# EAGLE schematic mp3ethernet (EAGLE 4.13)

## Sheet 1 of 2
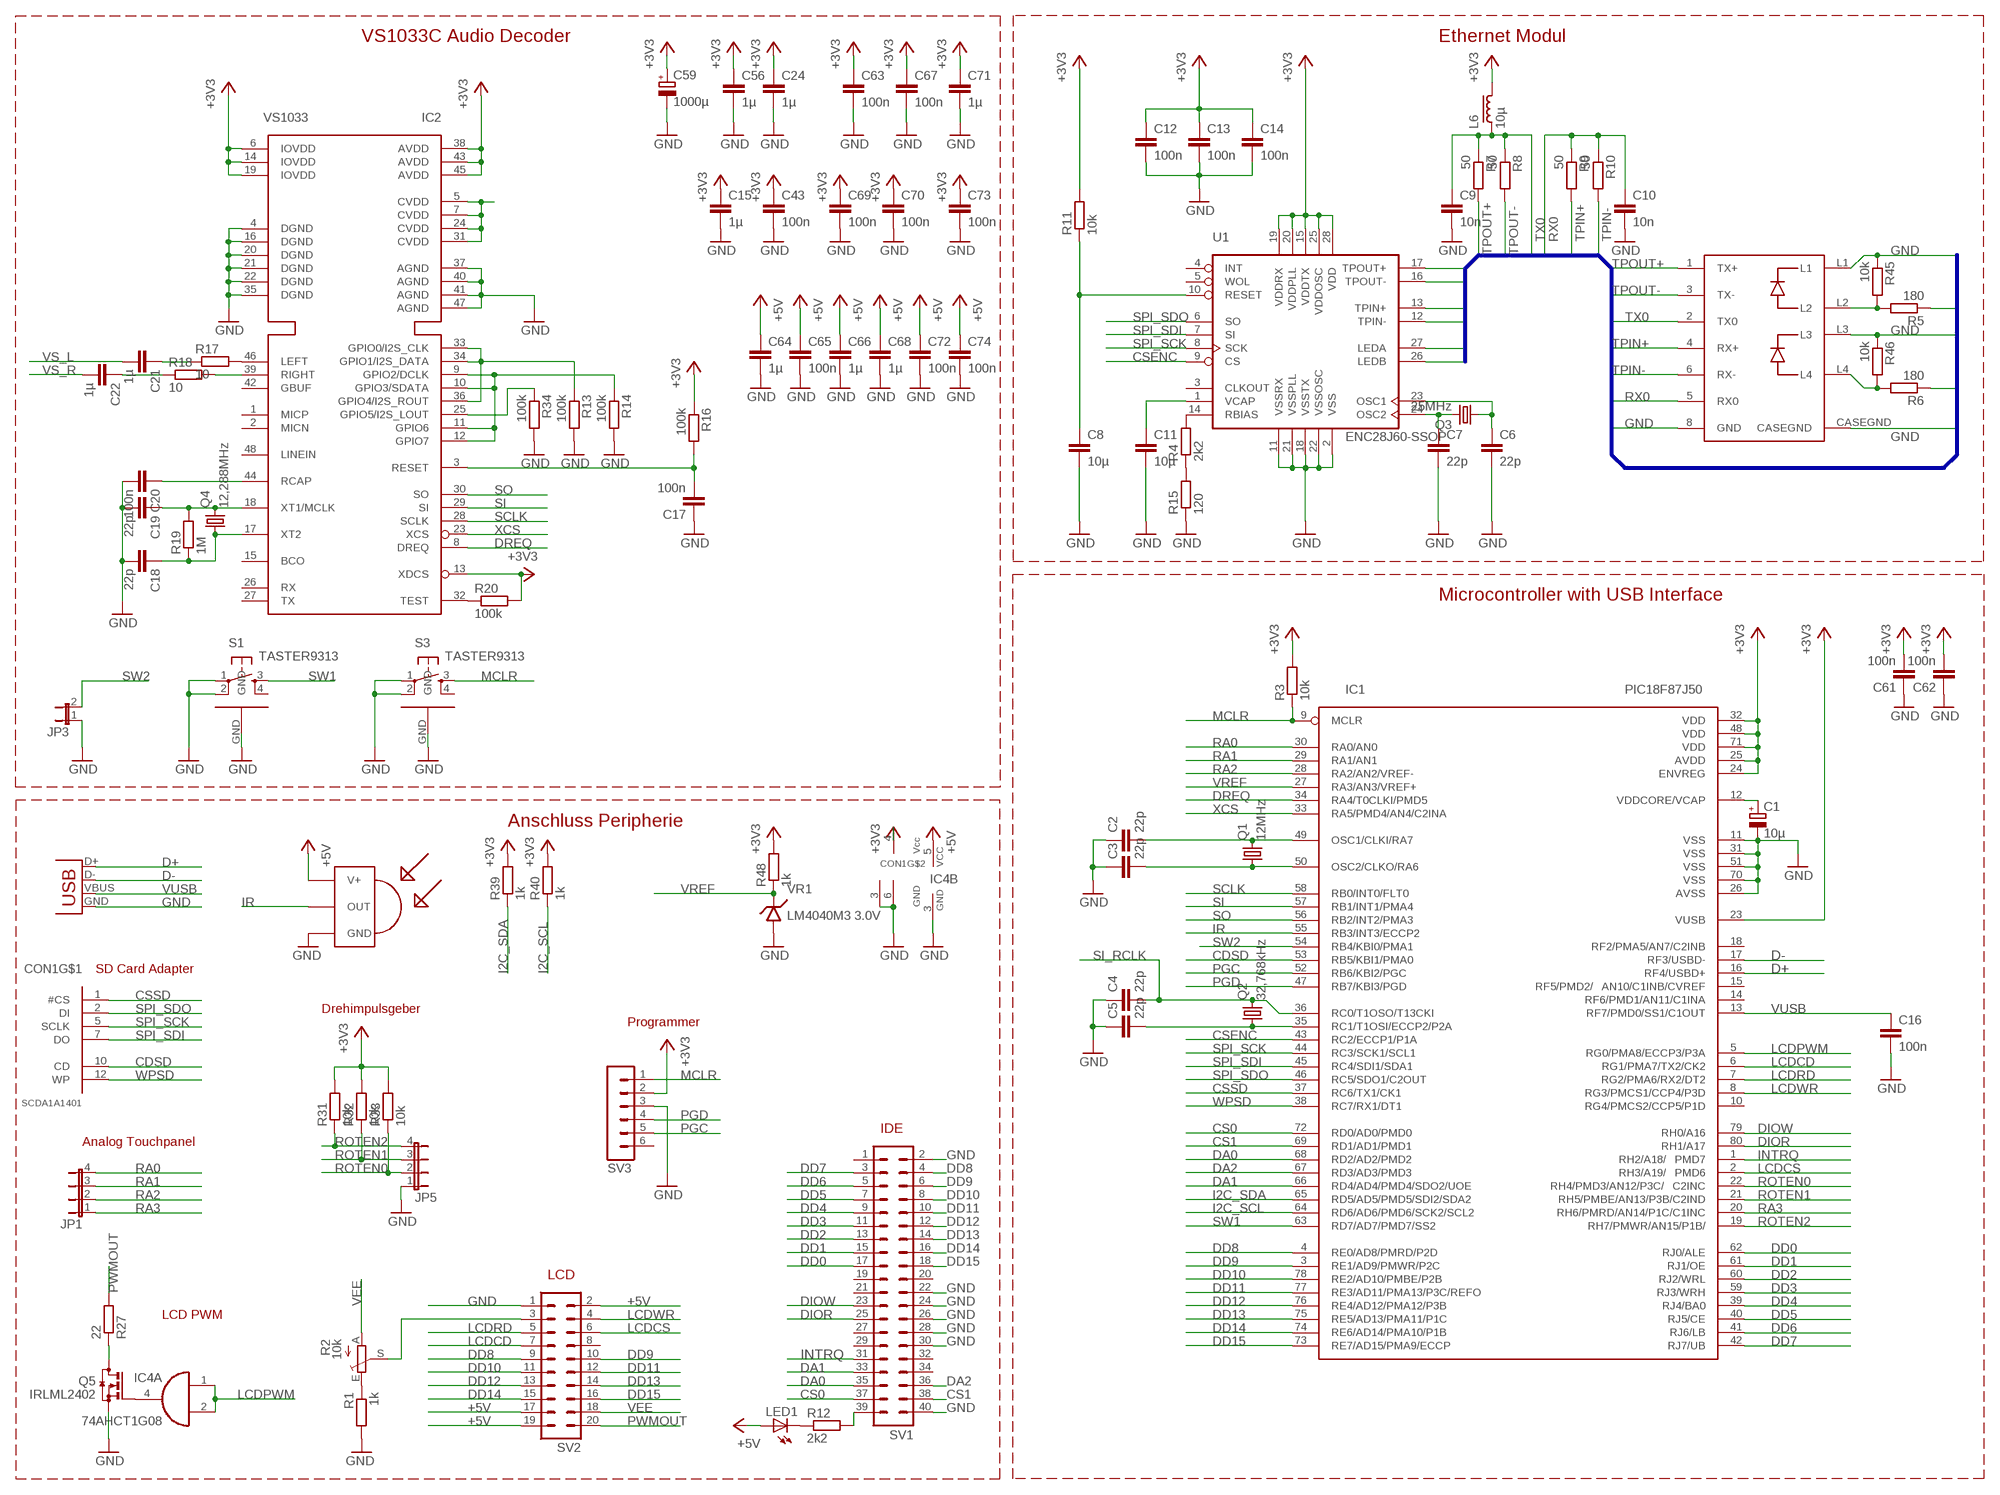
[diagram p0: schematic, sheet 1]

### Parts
BU1  1XRJ45_MM_JACK  [1XRJ45_MM_JACK]
C1  10µ  CPOL-EUE1.8-4  [E1,8-4]
C2  22p  C-EUC0805K  [C0805K]
C3  22p  C-EUC0805K  [C0805K]
C4  22p  C-EUC0805K  [C0805K]
C5  22p  C-EUC0805K  [C0805K]
C6  22p  C-EUC0805K  [C0805K]
C7  22p  C-EUC0805K  [C0805K]
C8  10µ  C-EUC0805K  [C0805K]
C9  10n  C-EUC0805K  [C0805K]
C10  10n  C-EUC0805K  [C0805K]
C11  10µ  C-EUC0805K  [C0805K]
C12  100n  C-EUC0805K  [C0805K]
C13  100n  C-EUC0805K  [C0805K]
C14  100n  C-EUC0805K  [C0805K]
C15  1µ  C-EUC0805K  [C0805K]
C16  100n  C-EUC0805K  [C0805K]
C17  100n  C-EUC0805K  [C0805K]
C18  22p  C-EUC0805K  [C0805K]
C19  22p  C-EUC0805K  [C0805K]
C20  100n  C-EUC0805K  [C0805K]
C21  1µ  C-EUC0805K  [C0805K]
C22  1µ  C-EUC0805K  [C0805K]
C24  1µ  C-EUC0805K  [C0805K]
C43  100n  C-EUC0805K  [C0805K]
C56  1µ  C-EUC0805K  [C0805K]
C59  1000µ  CPOL-EU150CLZ-0810  [150CLZ-0810]
C61  100n  C-EUC0805K  [C0805K]
C62  100n  C-EUC0805K  [C0805K]
C63  100n  C-EUC0805K  [C0805K]
C64  1µ  C-EUC0805K  [C0805K]
C65  100n  C-EUC0805K  [C0805K]
C66  1µ  C-EUC0805K  [C0805K]
C67  100n  C-EUC0805K  [C0805K]
C68  1µ  C-EUC0805K  [C0805K]
C69  100n  C-EUC0805K  [C0805K]
C70  100n  C-EUC0805K  [C0805K]
C71  1µ  C-EUC0805K  [C0805K]
C72  100n  C-EUC0805K  [C0805K]
C73  100n  C-EUC0805K  [C0805K]
C74  100n  C-EUC0805K  [C0805K]
CON1  SCDA1A1401  [SDCA1A1401]
IC1  PIC18F87J50  [SQFP-S-12X12-80]
IC2  VS1033  [SQFP-S-7X7-48]
IC4  74AHCT1G08  74AHTC1G08  [SOT23-5]
IC13  TSOP1836  [TSOP18XX]
JP1  JP4E  [JP4]
JP3  JP1E  [JP1]
JP5  JP4E  [JP4]
L6  10µ  L-PM1210  [PM1210]
LED1  LEDCHIPLED_0805  [CHIPLED_0805]
Q1  12MHz  CRYTALSM49  [SM49]
Q2  32,768kHz  CRYTALTC26V  [TC26V]
Q3  25MHz  CRYTALHC49UP  [HC49UP]
Q4  12,288MHz  CRYTALSM49  [SM49]
Q5  IRLML2402  BSS123  [SOT23]
R1  1k  R-EU_M0805  [M0805]
R2  10k  TRIM_EU-S64W  [S64W]
R3  10k  R-EU_R0805  [R0805]
R4  2k2  R-EU_R0805  [R0805]
R5  180  R-EU_R0805  [R0805]
R6  180  R-EU_R0805  [R0805]
R7  50  R-EU_R0805  [R0805]
R8  50  R-EU_R0805  [R0805]
R9  50  R-EU_R0805  [R0805]
R10  50  R-EU_R0805  [R0805]
R11  10k  R-EU_R0805  [R0805]
R12  2k2  R-EU_R0805  [R0805]
R13  100k  R-EU_R0805  [R0805]
R14  100k  R-EU_R0805  [R0805]
R15  120  R-EU_R0805  [R0805]
R16  100k  R-EU_R0805  [R0805]
R17  10  R-EU_R0805  [R0805]
R18  10  R-EU_R0805  [R0805]
R19  1M  R-EU_R0805  [R0805]
R20  100k  R-EU_R0805  [R0805]
R27  22  R-EU_R0805  [R0805]
R31  10k  R-EU_R0805  [R0805]
R32  10k  R-EU_R0805  [R0805]
R33  10k  R-EU_R0805  [R0805]
R34  100k  R-EU_R0805  [R0805]
R39  1k  R-EU_R0805  [R0805]
R40  1k  R-EU_R0805  [R0805]
R45  10k  R-EU_R0805  [R0805]
R46  10k  R-EU_R0805  [R0805]
R48  1k  R-EU_R0805  [R0805]
S1  TASTER9313  [TASTER9313]
S3  TASTER9313  [TASTER9313]
SV1  ML40  [ML40]
SV2  ML20  [ML20]
SV3  MA06-1  [MA06-1]
U1  ENC28J60-SSOP  [SSOP28]
VR1  LM4040M3 3.0V  LM4040M3  [SOT23]
X1  USB-MB-H  [USB-MB-H]

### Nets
+3V3: C12.1 C13.1 C14.1 C15.1 C24.1 C43.1 C56.1 C59.+ C61.2 C62.2 C63.1 C67.1 C69.1 C70.1 C71.1 C73.1 CON1.4(VCC) IC1.23(VUSB) IC1.24(ENVREG) IC1.25(AVDD) IC1.32(VDD) IC1.48(VDD) IC1.71(VDD) IC2.6(IOVDD) IC2.13(XDCS) IC2.14(IOVDD) IC2.19(IOVDD) IC2.38(AVDD) IC2.43(AVDD) IC2.45(AVDD) L6.2 R3.2 R11.2 R16.1 R20.2 R31.2 R32.2 R33.2 R39.2 R40.2 R48.2 SV3.2 U1.15(VDDTX) U1.19(VDDRX) U1.20(VDDPLL) U1.25(VDDOSC) U1.28(VDD) ; also sheet 2
+5V: C64.1 C65.1 C66.1 C68.1 C72.1 C74.1 IC4.5(B:VCC) IC13.VCC(V+) LED1.A SV2.2 SV2.17 SV2.19 ; also sheet 2
CDSD: CON1.10(CD) IC1.53(RB5/KBI1/PMA0)
CS0: IC1.72(RD0/AD0/PMD0) SV1.37
CS1: IC1.69(RD1/AD1/PMD1) SV1.38
CSENC: IC1.43(RC2/ECCP1/P1A) U1.9(CS)
CSSD: CON1.1(#CS) IC1.37(RC6/TX1/CK1)
D+: IC1.16(RF4/USBD+) X1.D+
D-: IC1.17(RF3/USBD-) X1.D-
DA0: IC1.68(RD2/AD2/PMD2) SV1.35
DA1: IC1.66(RD4/AD4/PMD4/SDO2/UOE) SV1.33
DA2: IC1.67(RD3/AD3/PMD3) SV1.36
DD0: IC1.62(RJ0/ALE) SV1.17
DD1: IC1.61(RJ1/OE) SV1.15
DD2: IC1.60(RJ2/WRL) SV1.13
DD3: IC1.59(RJ3/WRH) SV1.11
DD4: IC1.39(RJ4/BA0) SV1.9
DD5: IC1.40(RJ5/CE) SV1.7
DD6: IC1.41(RJ6/LB) SV1.5
DD7: IC1.42(RJ7/UB) SV1.3
DD8: IC1.4(RE0/AD8/PMRD/P2D) SV1.4 SV2.9
DD9: IC1.3(RE1/AD9/PMWR/P2C) SV1.6 SV2.10
DD10: IC1.78(RE2/AD10/PMBE/P2B) SV1.8 SV2.11
DD11: IC1.77(RE3/AD11/PMA13/P3C/REFO) SV1.10 SV2.12
DD12: IC1.76(RE4/AD12/PMA12/P3B) SV1.12 SV2.13
DD13: IC1.75(RE5/AD13/PMA11/P1C) SV1.14 SV2.14
DD14: IC1.74(RE6/AD14/PMA10/P1B) SV1.16 SV2.15
DD15: IC1.73(RE7/AD15/PMA9/ECCP) SV1.18 SV2.16
DIOR: IC1.80(RH1/A17) SV1.25
DIOW: IC1.79(RH0/A16) SV1.23
DREQ: IC1.34(RA4/T0CLKI/PMD5) IC2.8(DREQ)
GND: BU1.8(GND) BU1.CASEGND BU1.L1 BU1.L3 C1.- C2.1 C3.1 C4.1 C5.1 C6.2 C7.2 C8.2 C9.2 C10.2 C11.2 C12.2 C13.2 C14.2 C15.2 C16.2 C17.1 C18.2 C19.2 C20.2 C24.2 C43.2 C56.2 C59.- C61.1 C62.1 C63.2 C64.2 C65.2 C66.2 C67.2 C68.2 C69.2 C70.2 C71.2 C72.2 C73.2 C74.2 CON1.3(GND) CON1.6(GND) IC1.11(VSS) IC1.26(AVSS) IC1.31(VSS) IC1.51(VSS) IC1.70(VSS) IC2.4(DGND) IC2.16(DGND) IC2.20(DGND) IC2.21(DGND) IC2.22(DGND) IC2.35(DGND) IC2.37(AGND) IC2.40(AGND) IC2.41(AGND) IC2.47(AGND) IC4.3(B:GND) IC13.GND JP3.1 JP5.1 Q5.2(S) R1.2 R13.2 R14.2 R15.1 R34.2 R45.1 R46.1 S1.1(P) S1.2(P1) S1.GND S3.1(P) S3.2(P1) S3.GND SV1.2 SV1.22 SV1.24 SV1.26 SV1.28 SV1.30 SV1.40 SV2.1 SV3.3 U1.2(VSS) U1.11(VSSRX) U1.18(VSSTX) U1.21(VSSPLL) U1.22(VSSOSC) VR1.2 X1.GND ; also sheet 2
I2C_SCL: IC1.64(RD6/AD6/PMD6/SCK2/SCL2) R40.1 ; also sheet 2
I2C_SDA: IC1.65(RD5/AD5/PMD5/SDI2/SDA2) R39.1 ; also sheet 2
INTRQ: IC1.1(RH2/A18/PMD7) SV1.31
IR: IC1.55(RB3/INT3/ECCP2) IC13.OUT
LCDCD: IC1.6(RG1/PMA7/TX2/CK2) SV2.7
LCDCS: IC1.2(RH3/A19/PMD6) SV2.6
LCDPWM: IC1.5(RG0/PMA8/ECCP3/P3A) IC4.1(A:I0) IC4.2(A:I1)
LCDRD: IC1.7(RG2/PMA6/RX2/DT2) SV2.5
LCDWR: IC1.8(RG3/PMCS1/CCP4/P3D) SV2.4
LEDA: R5.1 U1.27(LEDA)
LEDB: R6.1 U1.26(LEDB)
MCLR: IC1.9(MCLR) R3.1 S3.3(S) SV3.1
N$1: C2.2 IC1.49(OSC1/CLKI/RA7) Q1.2
N$2: C3.2 IC1.50(OSC2/CLKO/RA6) Q1.1
N$3: C5.2 IC1.35(RC1/T1OSI/ECCP2/P2A) Q2.1
N$5: R2.S SV2.3
N$7: R12.2 SV1.39
N$8: C17.2 IC2.3(RESET) R16.2
N$9: C1.+ IC1.12(VDDCORE/VCAP)
N$10: IC2.46(LEFT) R17.2
N$11: R1.1 R2.E
N$12: BU1.L2 R5.2 R45.2
N$13: C7.1 Q3.2 U1.24(OSC2)
N$14: C6.1 Q3.1 U1.23(OSC1)
N$15: C8.1 R11.1 U1.10(RESET)
N$16: R4.2 U1.14(RBIAS)
N$17: C11.1 U1.1(VCAP)
N$18: BU1.L4 R6.2 R46.2
N$19: C19.1 IC2.18(XT1/MCLK) Q4.2 R19.2
N$20: C18.1 IC2.17(XT2) Q4.1 R19.1
N$21: Q5.3(D) R27.1
N$22: IC2.39(RIGHT) R18.2
N$23: LED1.C R12.1
N$25: IC2.25(GPIO5/I2S_LOUT) R34.1
N$27: IC4.4(A:O) Q5.1(G)
N$28: C21.1 R17.1
N$29: C20.1 IC2.44(RCAP)
N$30: IC2.32(TEST) R20.1
N$31: C22.1 R18.1
N$55: IC2.33(GPIO0/I2S_CLK) IC2.34(GPIO1/I2S_DATA) IC2.36(GPIO4/I2S_ROUT) R13.1
N$56: IC2.9(GPIO2/DCLK) IC2.10(GPIO3/SDATA) IC2.11(GPIO6) IC2.12(GPIO7) R14.1
N$69: R4.1 R15.2
PGC: IC1.52(RB6/KBI2/PGC) SV3.5
PGD: IC1.47(RB7/KBI3/PGD) SV3.4
PWMOUT: R27.2 SV2.20
RA0: IC1.30(RA0/AN0) JP1.4
RA1: IC1.29(RA1/AN1) JP1.3
RA2: IC1.28(RA2/AN2/VREF-) JP1.2
RA3: IC1.20(RH6/PMRD/AN14/P1C/C1INC) JP1.1
ROTEN0: IC1.22(RH4/PMD3/AN12/P3C/C2INC) JP5.2 R33.1
ROTEN1: IC1.21(RH5/PMBE/AN13/P3B/C2IND) JP5.3 R32.1
ROTEN2: IC1.19(RH7/PMWR/AN15/P1B/) JP5.4 R31.1
RX0: BU1.5(RX0) C10.1 R9.1 R10.1
SCLK: IC1.58(RB0/INT0/FLT0) IC2.28(SCLK)
SI: IC1.57(RB1/INT1/PMA4) IC2.29(SI)
SI_RCLK: C4.2 IC1.36(RC0/T1OSO/T13CKI) Q2.2 ; also sheet 2
SO: IC1.56(RB2/INT2/PMA3) IC2.30(SO)
SPI_SCK: CON1.5(SCLK) IC1.44(RC3/SCK1/SCL1) U1.8(SCK)
SPI_SDI: CON1.7(DO) IC1.45(RC4/SDI1/SDA1) U1.7(SI)
SPI_SDO: CON1.2(DI) IC1.46(RC5/SDO1/C2OUT) U1.6(SO)
SW1: IC1.63(RD7/AD7/PMD7/SS2) S1.3(S)
SW2: IC1.54(RB4/KBI0/PMA1) JP3.2
TPIN+: BU1.4(RX+) R9.2 U1.13(TPIN+)
TPIN-: BU1.6(RX-) R10.2 U1.12(TPIN-)
TPOUT+: BU1.1(TX+) R7.2 U1.17(TPOUT+)
TPOUT-: BU1.3(TX-) R8.2 U1.16(TPOUT-)
TX0: BU1.2(TX0) C9.1 L6.1 R7.1 R8.1
VDD_2,5: IC2.5(CVDD) IC2.7(CVDD) IC2.24(CVDD) IC2.31(CVDD) ; also sheet 2
VEE: R2.A SV2.18
VREF: IC1.27(RA3/AN3/VREF+) R48.1 VR1.1
VS_L: C21.2 ; also sheet 2
VS_R: C22.2 ; also sheet 2
VUSB: C16.1 IC1.13(RF7/PMD0/SS1/C1OUT) X1.VBUS
WPSD: CON1.12(WP) IC1.38(RC7/RX1/DT1)
XCS: IC1.33(RA5/PMD4/AN4/C2INA) IC2.23(XCS)
Unconnected: IC1.10(RG4/PMCS2/CCP5/P1D) IC1.14(RF6/PMD1/AN11/C1INA) IC1.15(RF5/PMD2/AN10/C1INB/CVREF) IC1.18(RF2/PMA5/AN7/C2INB) IC2.1(MICP) IC2.2(MICN) IC2.15(BCO) IC2.26(RX) IC2.27(TX) IC2.42(GBUF) IC2.48(LINEIN) S1.4(S1) S3.4(S1) SV1.1 SV1.19 SV1.20 SV1.21 SV1.27 SV1.29 SV1.32 SV1.34 SV2.8 SV3.6 U1.3(CLKOUT) U1.4(INT) U1.5(WOL)

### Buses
TPOUT+,TPOUT-,TPIN+,TPIN-,LEDA,LEDB,GND,TX0,RX0

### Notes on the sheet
- VS1033C Audio Decoder | Ethernet Modul
- Microcontroller with USB Interface
- Anschluss Peripherie
- SD Card Adapter
- Drehimpulsgeber
- Programmer
- IDE
- Analog Touchpanel
- LCD
- LCD PWM

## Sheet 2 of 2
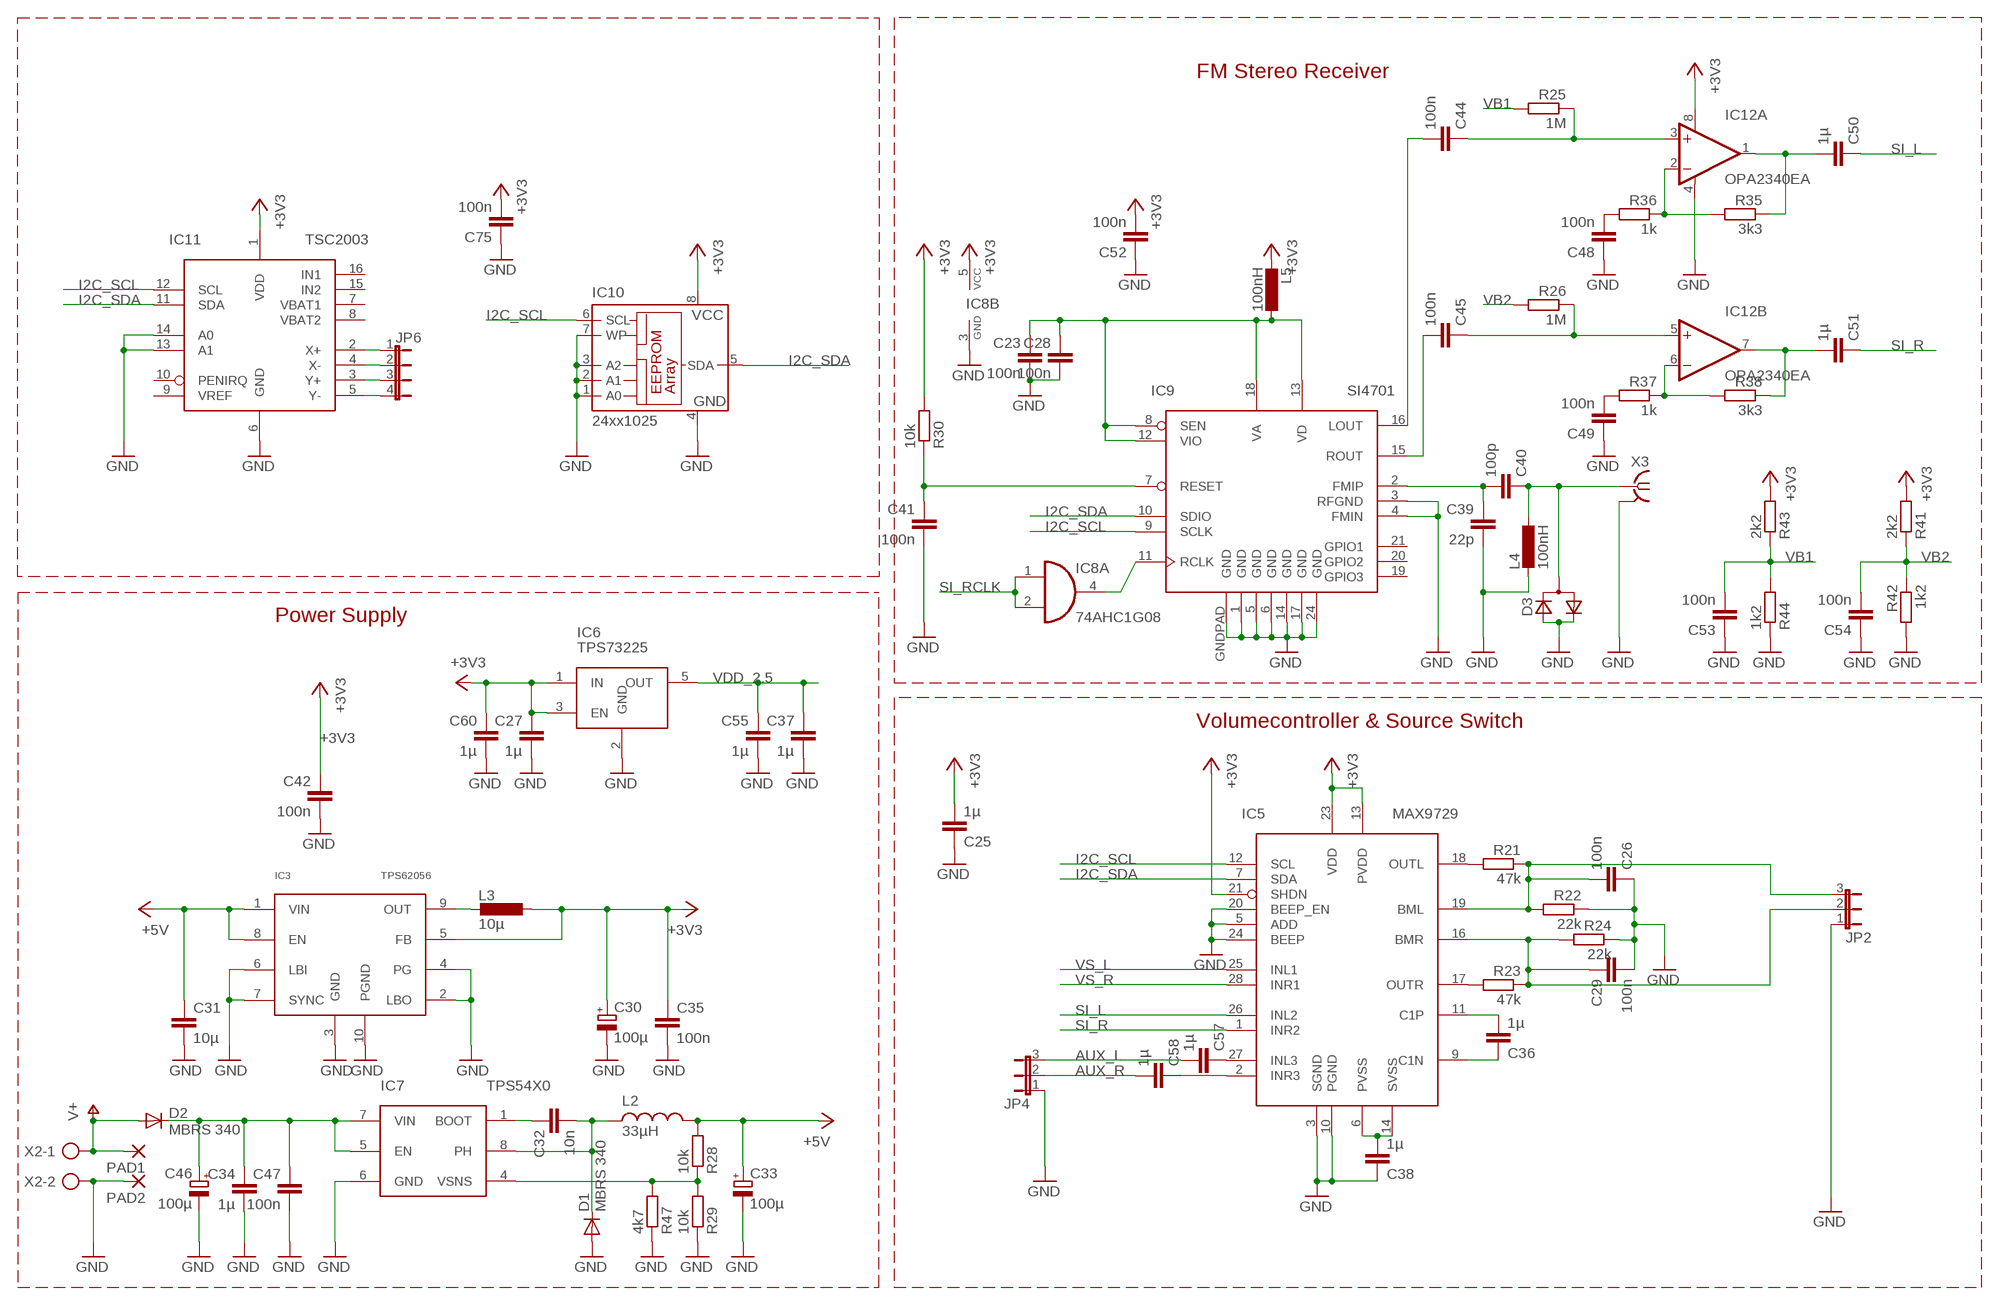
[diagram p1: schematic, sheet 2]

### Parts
C23  100n  C-EUC0805K  [C0805K]
C25  1µ  C-EUC0805K  [C0805K]
C26  100n  C-EUC0805K  [C0805K]
C27  1µ  C-EUC0805K  [C0805K]
C28  100n  C-EUC0805K  [C0805K]
C29  100n  C-EUC0805K  [C0805K]
C30  100µ  CPOL-EUCT7343  [CT7343]
C31  10µ  C-EUC0805K  [C0805K]
C32  10n  C-EUC0805K  [C0805K]
C33  100µ  CPOL-EUCT7343  [CT7343]
C34  1µ  C-EUC0805K  [C0805K]
C35  100n  C-EUC0805K  [C0805K]
C36  1µ  C-EUC0805K  [C0805K]
C37  1µ  C-EUC0805K  [C0805K]
C38  1µ  C-EUC0805K  [C0805K]
C39  22p  C-EUC0805K  [C0805K]
C40  100p  C-EUC0805K  [C0805K]
C41  100n  C-EUC0805K  [C0805K]
C42  100n  C-EUC0805K  [C0805K]
C44  100n  C-EUC0805K  [C0805K]
C45  100n  C-EUC0805K  [C0805K]
C46  100µ  CPOL-EUE2.5-6  [E2,5-6]
C47  100n  C-EUC0805K  [C0805K]
C48  100n  C-EUC0805K  [C0805K]
C49  100n  C-EUC0805K  [C0805K]
C50  1µ  C-EUC0805K  [C0805K]
C51  1µ  C-EUC0805K  [C0805K]
C52  100n  C-EUC0805K  [C0805K]
C53  100n  C-EUC0805K  [C0805K]
C54  100n  C-EUC0805K  [C0805K]
C55  1µ  C-EUC0805K  [C0805K]
C57  1µ  C-EUC0805K  [C0805K]
C58  1µ  C-EUC0805K  [C0805K]
C60  1µ  C-EUC0805K  [C0805K]
C75  100n  C-EUC0805K  [C0805K]
D1  MBRS 340  DIODE-SMC  [SMC]
D2  MBRS 340  DIODE-SMC  [SMC]
D3  D_ACACSOT23  [SOT-23]
IC3  TPS62056  TPS6205X  [MSOP10]
IC5  MAX9729  [QFN-28]
IC6  TPS73225  TPS732XX  [SOT23-5]
IC7  TPS54X0  [SO08]
IC8  74AHC1G08  74AHTC1G08  [SOT23-5]
IC9  SI4701  [S-PQFP-N24(RGE)]
IC10  24xx1025  24C01ASM  [SO-08M]
IC11  TSC2003  [TSSOP16]
IC12  OPA2340EA  OPA2658E  [MSOP08]
JP2  JP2E  [JP2]
JP4  JP2E  [JP2]
JP6  JP4E  [JP4]
L2  33µH  MSS1260  [MSS1260]
L3  10µ  PIS2408  [PIS2408]
L4  100nH  L-EUL0805  [L0805]
L5  100nH  L-EUL0805  [L0805]
PAD1  3,17/1,3  [3,17/1,3]
PAD2  3,17/1,3  [3,17/1,3]
R21  47k  R-EU_R0805  [R0805]
R22  22k  R-EU_R0805  [R0805]
R23  47k  R-EU_R0805  [R0805]
R24  22k  R-EU_R0805  [R0805]
R25  1M  R-EU_R0805  [R0805]
R26  1M  R-EU_R0805  [R0805]
R28  10k  R-EU_R0805  [R0805]
R29  10k  R-EU_R0805  [R0805]
R30  10k  R-EU_R0805  [R0805]
R35  3k3  R-EU_R0805  [R0805]
R36  1k  R-EU_R0805  [R0805]
R37  1k  R-EU_R0805  [R0805]
R38  3k3  R-EU_R0805  [R0805]
R41  2k2  R-EU_R0805  [R0805]
R42  1k2  R-EU_R0805  [R0805]
R43  2k2  R-EU_R0805  [R0805]
R44  1k2  R-EU_R0805  [R0805]
R47  4k7  R-EU_R0805  [R0805]
X2  AK500/2  [AK500/2]
X3  BU-SMB-V  [BU-SMB-V]

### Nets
+3V3: C25.2 C27.1 C30.+ C35.1 C42.1 C52.2 C60.1 C75.2 IC3.5(FB) IC5.13(PVDD) IC5.21(SHDN) IC5.23(VDD) IC6.1(IN) IC6.3(EN) IC8.5(B:VCC) IC10.8(VCC) IC11.1(VDD) IC12.8(A:V+) L3.P$2 L5.2 R30.2 R41.2 R43.2 ; also sheet 1
+5V: C31.1 C33.+ IC3.1(VIN) IC3.8(EN) L2.P$1 R28.2 ; also sheet 1
AUX_L: C57.2 JP4.3
AUX_R: C58.2 JP4.2
GND: C23.2 C25.1 C26.1 C27.2 C28.2 C29.2 C30.- C31.2 C33.- C34.2 C35.2 C37.2 C38.1 C39.2 C41.2 C42.2 C46.- C47.2 C48.1 C49.1 C52.1 C53.1 C54.1 C55.2 C60.2 C75.1 D1.A D3.2(C) D3.3(A) IC3.2(LBO) IC3.3(GND) IC3.4(PG) IC3.6(LBI) IC3.7(SYNC) IC3.10(PGND) IC5.3(SGND) IC5.5(ADD) IC5.10(PGND) IC5.20(BEEP_EN) IC5.24(BEEP) IC6.2(GND) IC7.6(GND) IC8.3(B:GND) IC9.1(GND) IC9.3(RFGND) IC9.4(FMIN) IC9.5(GND) IC9.6(GND) IC9.14(GND) IC9.17(GND) IC9.24(GND) IC9.GNDPAD(GND) IC10.1(A0) IC10.2(A1) IC10.3(A2) IC10.4(GND) IC10.7(WP) IC11.6(GND) IC11.13(A1) IC11.14(A0) IC12.4(A:V-) JP2.1 JP4.1 L4.2 PAD2.1(P) R22.1 R24.1 R29.1 R42.2 R44.1 R47.1 X2.2 X3.2(GND) ; also sheet 1
I2C_SCL: IC5.12(SCL) IC9.9(SCLK) IC10.6(SCL) IC11.12(SCL) ; also sheet 1
I2C_SDA: IC5.7(SDA) IC9.10(SDIO) IC10.5(SDA) IC11.11(SDA) ; also sheet 1
N$4: C44.2 IC9.16(LOUT)
N$24: C26.2 IC5.19(BML) JP2.3 R21.1 R22.2
N$26: IC11.2(X+) JP6.1
N$32: IC8.4(A:O) IC9.11(RCLK)
N$33: IC5.18(OUTL) R21.2
N$34: IC5.17(OUTR) R23.2
N$35: C29.1 IC5.16(BMR) JP2.2 R23.1 R24.2
N$36: C38.2 IC5.6(PVSS) IC5.14(SVSS)
N$37: C48.2 R36.2
N$38: C36.1 IC5.9(C1N)
N$39: IC3.9(OUT) L3.P$1
N$40: C36.2 IC5.11(C1P)
N$41: C49.2 R37.2
N$43: C32.2 D1.C IC7.8(PH) L2.P$2
N$44: C32.1 IC7.1(BOOT)
N$46: IC7.4(VSNS) R28.1 R29.2 R47.2
N$47: C34.1 C46.+ C47.1 D2.C IC7.5(EN) IC7.7(VIN)
N$48: C57.1 IC5.27(INL3)
N$49: C39.1 C40.2 IC9.2(FMIP)
N$50: C40.1 D3.1(CA) L4.1 X3.1
N$51: C41.1 IC9.7(RESET) R30.1
N$52: C45.2 IC9.15(ROUT)
N$53: C44.1 IC12.3(A:+IN) R25.1
N$54: C45.1 IC12.5(B:+IN) R26.1
N$57: IC12.2(A:-IN) R35.2 R36.1
N$58: C50.2 IC12.1(A:OUT) R35.1
N$59: IC12.6(B:-IN) R37.1 R38.2
N$60: C51.2 IC12.7(B:OUT) R38.1
N$61: IC11.4(X-) JP6.2
N$63: IC11.3(Y+) JP6.3
N$64: IC11.5(Y-) JP6.4
N$67: C58.1 IC5.2(INR3)
SI_L: C50.1 IC5.26(INL2)
SI_R: C51.1 IC5.1(INR2)
SI_RCLK: IC8.1(A:I0) IC8.2(A:I1) ; also sheet 1
SI_VDD: C23.1 C28.1 IC9.8(SEN) IC9.12(VIO) IC9.13(VD) IC9.18(VA) L5.1
V+: D2.A PAD1.1(P) X2.1
VB1: C53.2 R25.2 R43.1 R44.2
VB2: C54.2 R26.2 R41.1 R42.1
VDD_2,5: C37.1 C55.1 IC6.5(OUT) ; also sheet 1
VS_L: IC5.25(INL1) ; also sheet 1
VS_R: IC5.28(INR1) ; also sheet 1
Unconnected: IC9.19(GPIO3) IC9.20(GPIO2) IC9.21(GPIO1) IC11.7(VBAT1) IC11.8(VBAT2) IC11.9(VREF) IC11.10(PENIRQ) IC11.15(IN2) IC11.16(IN1)

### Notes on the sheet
- FM Stereo Receiver
- Power Supply
- Volumecontroller & Source Switch

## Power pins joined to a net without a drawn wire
GND: X3.3(GND) X3.4(GND) X3.5(GND)

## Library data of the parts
BU1 = con_MagJack:1XRJ45_MM_JACK
C1 C30 C33 C46 C59 = rcl:CPOL-EU: POLARIZED CAPACITOR, European symbol
C2-C29 C32 C34-C45 C47-C51 C53-C58 C60-C74 = rcl:C-EU: CAPACITOR, European symbol
C31 C52 C75 = rcl-2:C-EU: CAPACITOR, European symbol
CON1 = ALPS:SCDA1A1401
D1 D2 = diode:DIODE-: DIODE
D3 = zetex:D_ACAC: Dual DIODE
IC1 = eigene:PIC18F87J50
IC2 = eigene:VS1033
IC3 = Texas Instruments:TPS6205X
IC4 IC8 = logik:74AHTC1G08
IC5 = MAXIM:MAX9729: Stereo Headphone Amplifier with BassMax, Volume Control, and Input Mux
IC6 = Texas Instruments:TPS732XX
IC7 = Texas Instruments:TPS54X0: 2A Step-Down Converter Vin: 5.5 - 36V Vout: adj
IC9 = Silabs:SI4701
IC10 = microchip:24C*: Serial EEPROM 1 K/2 K/4 K
IC11 = Texas Instruments:TSC2003
IC12 = burr-brown:OPA2658: Dual Wideband, Low Power, Current Feedback Operational Amplifier
IC13 = tsop:TSOP1836: IR Receiver and Demodulator
JP1 JP5 JP6 = jumper:JP4E: JUMPER
JP2 JP4 = jumper:JP2E: JUMPER
JP3 = jumper:JP1E: JUMPER
L2 = inductor-coilcraft:MSS1260: SMT Power Inductor
L3 = inductors:PIS2408
L4 L5 = rcl-2:L-EU: INDUCTOR, European symbol
L6 = inductors-jwmiller:L: INDUCTORS
LED1 = led:LED: LED
PAD1 PAD2 = wirepad:3,17/1,3: THROUGH-HOLE PAD
Q1-Q4 = crystal:CRYTAL: CRYSTAL
Q5 = transistor-small-signal:BSS123: N-CHANNEL MOS FET
R1 R3-R48 = rcl:R-EU_: RESISTOR, European symbol
R2 = pot:TRIM_EU-: POTENTIOMETER
S1 S3 = TASTER9313:TASTER9313
SV1 = con-harting-ml:ML40: HARTING
SV2 = con-harting-ml:ML20: HARTING
SV3 = con-lstb:MA06-1: PIN HEADER
U1 = microchip-enc28j60:ENC28J60-*: Microchip 10Mbit Eth. contoller with SPI interface
VR1 = synthdiy:LM4040: Shunt VOLTAGE REG.
X1 = con-usb:USB: USB Connectors
X2 = con-ptr500:AK500/2: CONNECTOR
X3 = con-coax:BU-SMB-V: FEMALE SMB CONNECTOR Radiall distributor RS 112-2993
